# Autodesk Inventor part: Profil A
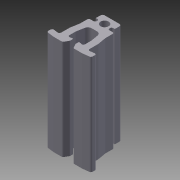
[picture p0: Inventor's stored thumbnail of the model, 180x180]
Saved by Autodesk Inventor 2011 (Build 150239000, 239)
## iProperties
Created: 2010-03
Part Number: Profil A
Document SubType Name: Modeling
Designer: ehttln
Density: 2.71 g/cm^3
Material: Aluminum-6061
Description: Profile Type A
Mass: 27.2456 g
Surface Area: 70.5482 cm^2
Volume: 10.0537 cm^3
Author: ehttln
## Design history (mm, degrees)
sketch "Sketch1"
  geometry: L1 (-6.364, -5.908)-(-6.357, -5.911); L2 (-1.315, -5.111)-(-1.326, -5.113); L3 (1.314, -5.111)-(-1.315, -5.111); L4 (1.297, -5.113)-(1.314, -5.111); L5 (-3.277, -6.75)-(-3.258, -6.749); L6 (-7.107, -10.229)-(-6.37, -6.038); L7 (-3.932, -10.509)-(-3.94, -10.505); L8 (-3.951, -10.642)-(-3.944, -10.636); L9 (-3.258, -6.749)-(-3.932, -10.509); L10 (-7.126, -14.693)-(-7.119, -14.687); L11 (-7.119, -18.345)-(-10.421, -17.938); L12 (-10.421, -17.938)-(-10.436, -17.94); L13 (-10.231, -15.195)-(-7.963, -15.478); L14 (-10.244, -15.2)-(-10.231, -15.195); L15 (-11.127, -17.159)-(-11.12, -17.163); L16 (-11.12, -17.163)-(-11.12, -15.982); L17 (-11.12, -15.982)-(-11.127, -15.981); L18 (-3.163, -18.345)-(-7.119, -18.345); L19 (3.894, -1.555)-(5.581, -1.555); L20 (5.581, -1.555)-(5.574, -1.557); L21 (7.105, -14.687)-(7.098, -14.693); L22 (7.981, -15.474)-(7.994, -15.474); L23 (10.229, -15.195)-(10.215, -15.2); L24 (7.994, -15.474)-(10.229, -15.195); L25 (10.429, -17.937)-(7.105, -18.345); L26 (11.105, -17.163)-(11.098, -17.159); L27 (11.105, -15.982)-(11.105, -17.163); L28 (11.098, -15.981)-(11.105, -15.982); L29 (-3.754, 3.728)-(3.739, 3.728); L30 (-3.182, -0.768)-(-3.182, -0.438); L31 (-3.189, -0.77)-(-3.182, -0.768); L32 (-3.182, -0.438)-(-3.189, -0.439); L33 (-3.977, 0.348)-(-3.97, 0.35); L34 (-4.77, 0.35)-(-4.77, 2.712); L35 (-4.77, 2.712)-(-4.777, 2.71); L36 (-3.761, 3.726)-(-3.754, 3.728); L37 (-3.027, -14.495)-(-3.017, -14.496); L38 (-2.522, -17.951)-(-2.535, -17.953); L39 (-1.493, -16.173)-(-2.522, -17.951); L40 (-3.017, -14.496)-(-1.684, -14.255); L41 (-1.684, -14.255)-(-1.697, -14.261); L42 (-1.399, -14.511)-(-1.392, -14.509); L43 (-1.392, -14.509)-(-1.392, -15.779); L44 (-1.392, -15.779)-(-1.399, -15.773); L45 (-1.504, -16.167)-(-1.493, -16.173); L46 (-6.37, -6.038)-(-6.376, -6.045); L47 (6.336, -2.319)-(6.343, -2.317); L48 (6.343, -5.911)-(6.336, -5.908); L49 (6.343, -2.317)-(6.343, -5.911); L50 (6.348, -6.044)-(6.355, -6.038); L51 (3.257, -6.749)-(3.248, -6.75); L52 (6.355, -6.038)-(7.092, -10.229); L53 (3.917, -10.509)-(3.257, -6.749); L54 (7.105, -10.369)-(7.105, -14.687); L55 (7.098, -10.364)-(7.105, -10.369); L56 (7.092, -10.229)-(7.086, -10.227); L57 (3.93, -13.722)-(3.93, -10.636); L58 (3.93, -10.636)-(3.923, -10.642); L59 (3.911, -10.505)-(3.917, -10.509); L60 (-7.115, -10.227)-(-7.107, -10.229); L61 (-7.119, -10.369)-(-7.126, -10.364); L62 (-7.119, -14.687)-(-7.119, -10.369); L63 (-3.944, -13.722)-(-3.951, -13.72); L64 (-3.944, -10.636)-(-3.944, -13.722)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; C1 r 2.032 at (-0.007, -0.002); A1 r 1.981 centre (-1.326, -7.094) between (-1.326, -5.113) and (-3.277, -6.75); A2 r 0.787 centre (-3.164, -10.642) between (-3.94, -10.505) and (-3.951, -10.642); A3 r 0.787 centre (-7.914, -14.693) between (-7.963, -15.478) and (-7.126, -14.693); A4 r 0.787 centre (-10.34, -17.159) between (-11.127, -17.159) and (-10.436, -17.94); A5 r 0.787 centre (-10.34, -15.981) between (-10.244, -15.2) and (-11.127, -15.981); A6 r 0.787 centre (-3.164, -13.72) between (-3.951, -13.72) and (-3.027, -14.495); A7 r 0.787 centre (3.948, -0.77) between (3.161, -0.77) and (3.894, -1.555); A8 r 0.762 centre (5.574, -2.319) between (6.336, -2.319) and (5.574, -1.557); A9 r 0.787 centre (7.885, -14.693) between (7.098, -14.693) and (7.981, -15.474); A10 r 0.787 centre (10.311, -15.981) between (11.098, -15.981) and (10.215, -15.2); A11 r 0.787 centre (10.311, -17.159) between (10.429, -17.937) and (11.098, -17.159); A12 r 1.016 centre (-3.761, 2.71) between (-3.761, 3.726) and (-4.777, 2.71); A13 r 0.787 centre (-3.217, -17.559) between (-3.163, -18.345) and (-2.535, -17.953); A14 r 0.254 centre (-1.653, -14.511) between (-1.399, -14.511) and (-1.697, -14.261); A15 r 0.787 centre (-2.186, -15.773) between (-1.504, -16.167) and (-1.399, -15.773); A16 r 0.787 centre (-7.152, -5.908) between (-6.376, -6.045) and (-6.364, -5.908); A17 r 0.787 centre (7.123, -5.908) between (6.336, -5.908) and (6.348, -6.044); A18 r 1.981 centre (1.297, -7.094) between (3.248, -6.75) and (1.297, -5.113); A19 r 0.787 centre (6.31, -10.364) between (7.098, -10.364) and (7.086, -10.227); A20 r 0.787 centre (3.135, -10.642) between (3.923, -10.642) and (3.911, -10.505); A21 r 0.787 centre (-6.339, -10.364) between (-7.115, -10.227) and (-7.126, -10.364); A22 r 1.016 centre (3.732, 2.71) between (4.748, 2.71) and (3.732, 3.726); A23 r 0.787 centre (3.948, -0.439) between (3.948, 0.348) and (3.161, -0.439); A24 r 0.787 centre (-3.977, -0.77) between (-4.031, -1.555) and (-3.189, -0.77); A25 r 0.762 centre (-5.602, -2.319) between (-5.602, -1.557) and (-6.364, -2.319); A26 r 0.787 centre (-3.977, -0.439) between (-3.189, -0.439) and (-3.977, 0.348); A27 r 0.787 centre (3.135, -13.72) between (3.052, -14.503) and (3.923, -13.72); A28 r 0.787 centre (3.188, -17.559) between (2.506, -17.953) and (3.188, -18.346); A29 r 0.254 centre (1.624, -14.511) between (1.668, -14.261) and (1.377, -14.451); A30 r 0.787 centre (2.157, -15.773) between (1.37, -15.773) and (1.475, -16.167); 1 further point
  constraints: 174 end point, 60 point on circle, 31 centre point
extrude "Extrusion1" new body sketch "Sketch1" distance "d0" = 50; taper "d1" = 0 deg
body "Solid1"
